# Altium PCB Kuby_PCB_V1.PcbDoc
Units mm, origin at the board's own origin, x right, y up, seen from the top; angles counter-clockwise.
Board outline 122.6 x 93.98 mm, 2 copper layers (Top Layer, Bottom Layer), stack 1.671 mm thick; 16 components, 29 nets, 97 pads, 0 vias.
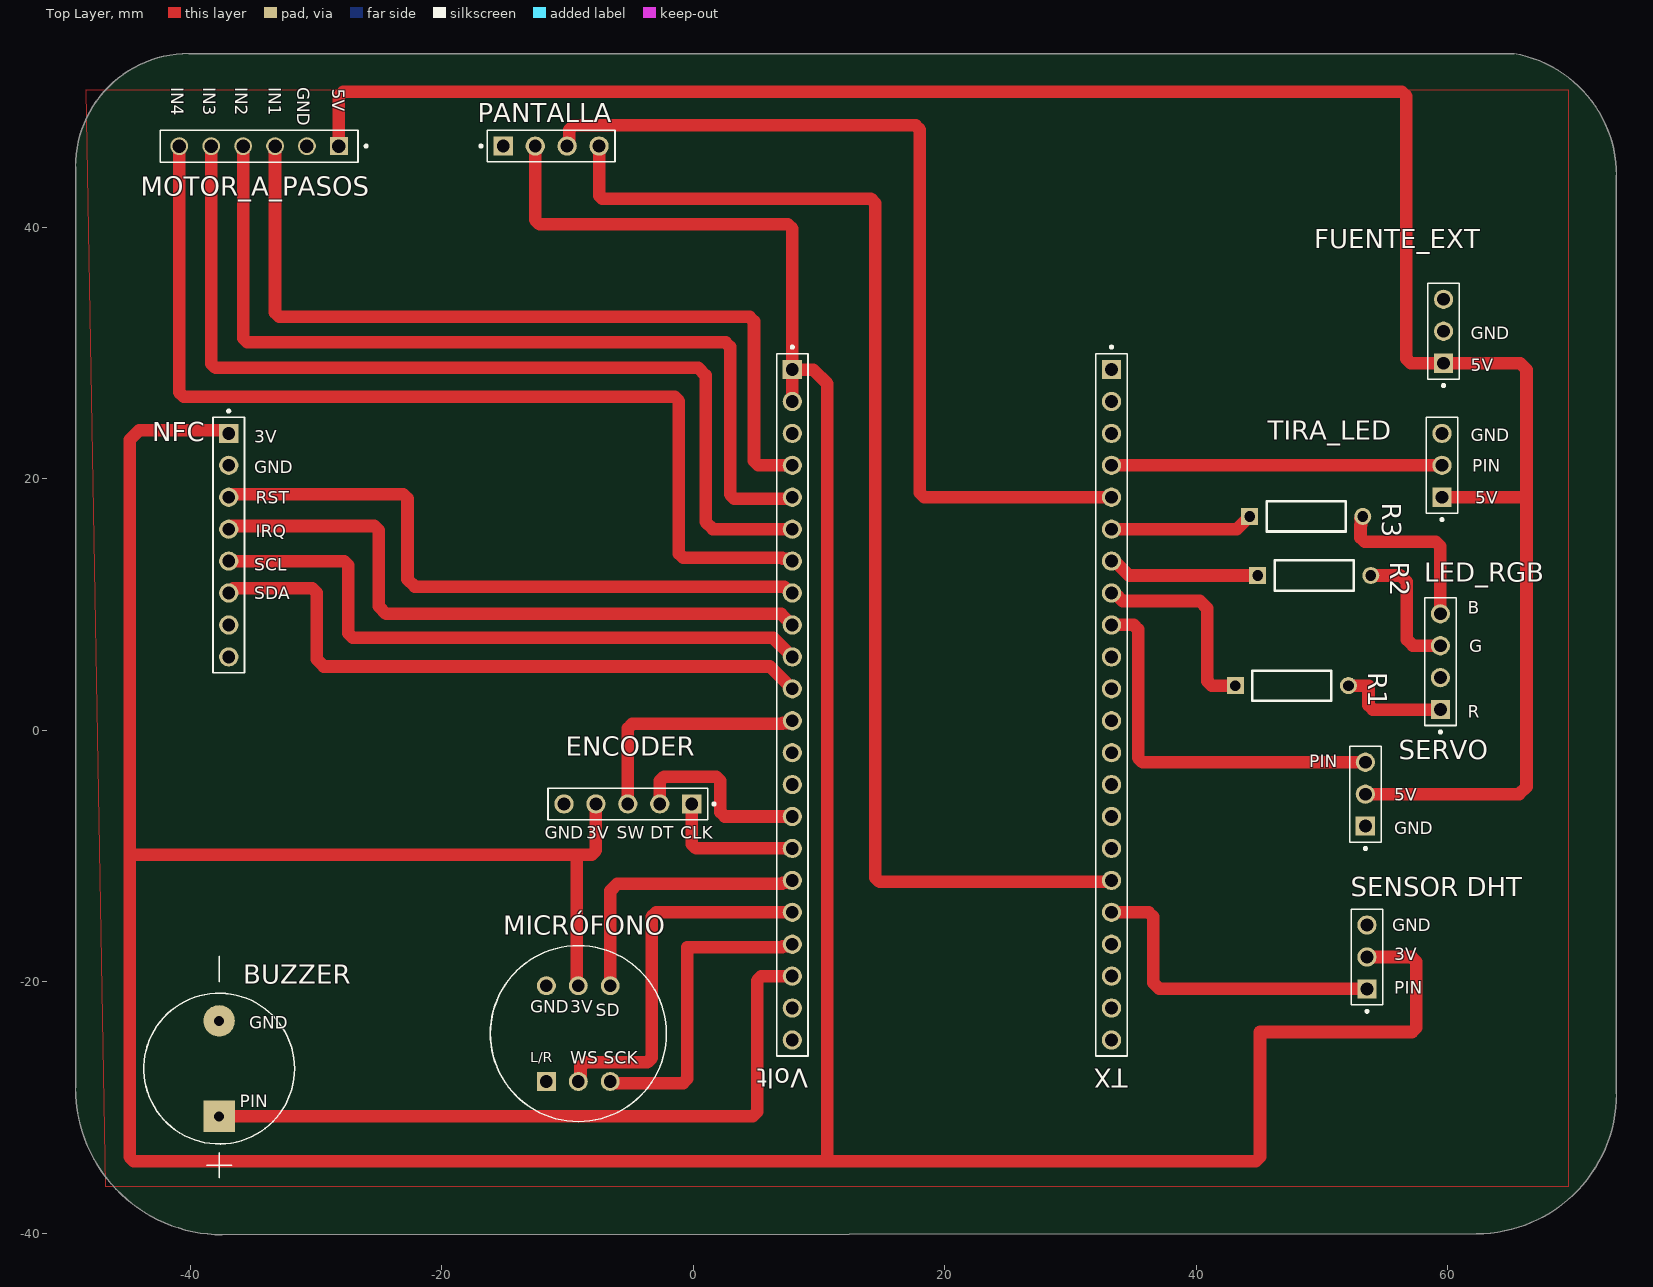
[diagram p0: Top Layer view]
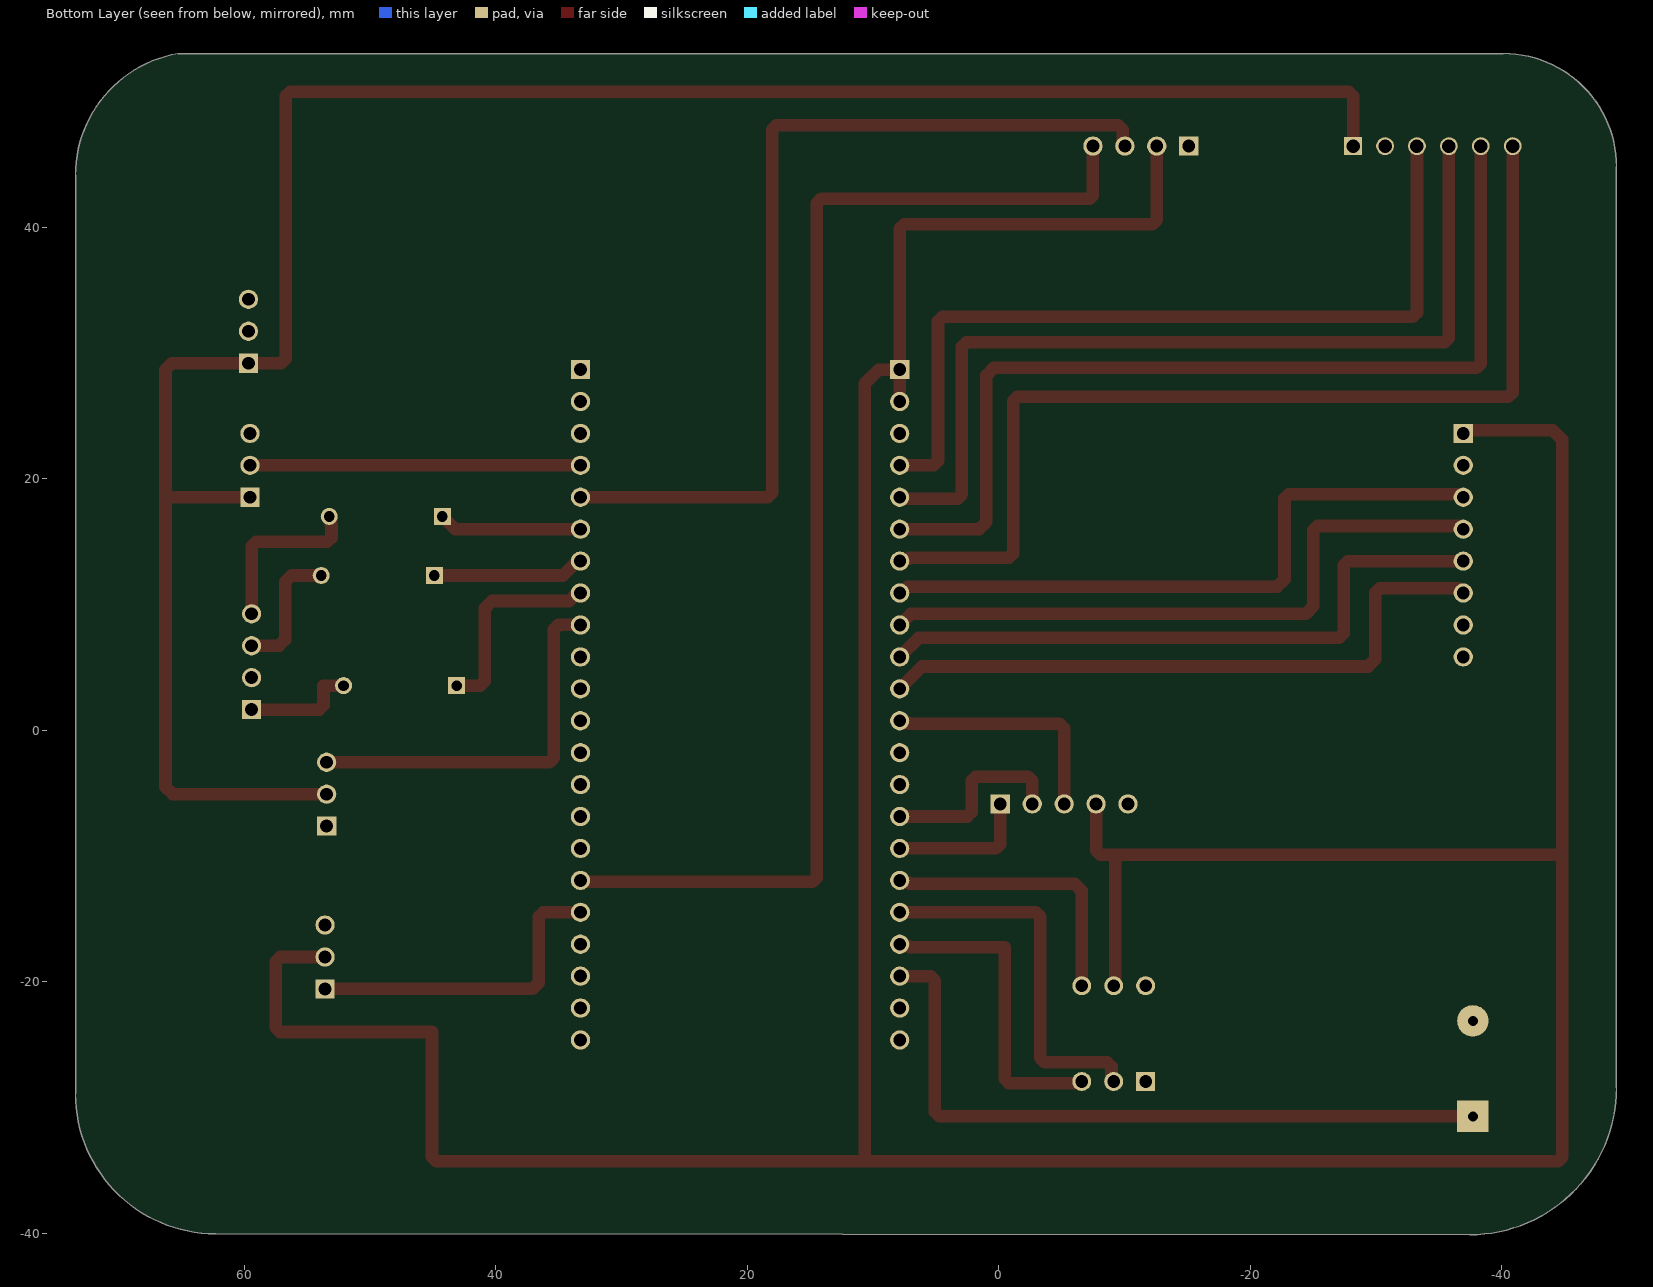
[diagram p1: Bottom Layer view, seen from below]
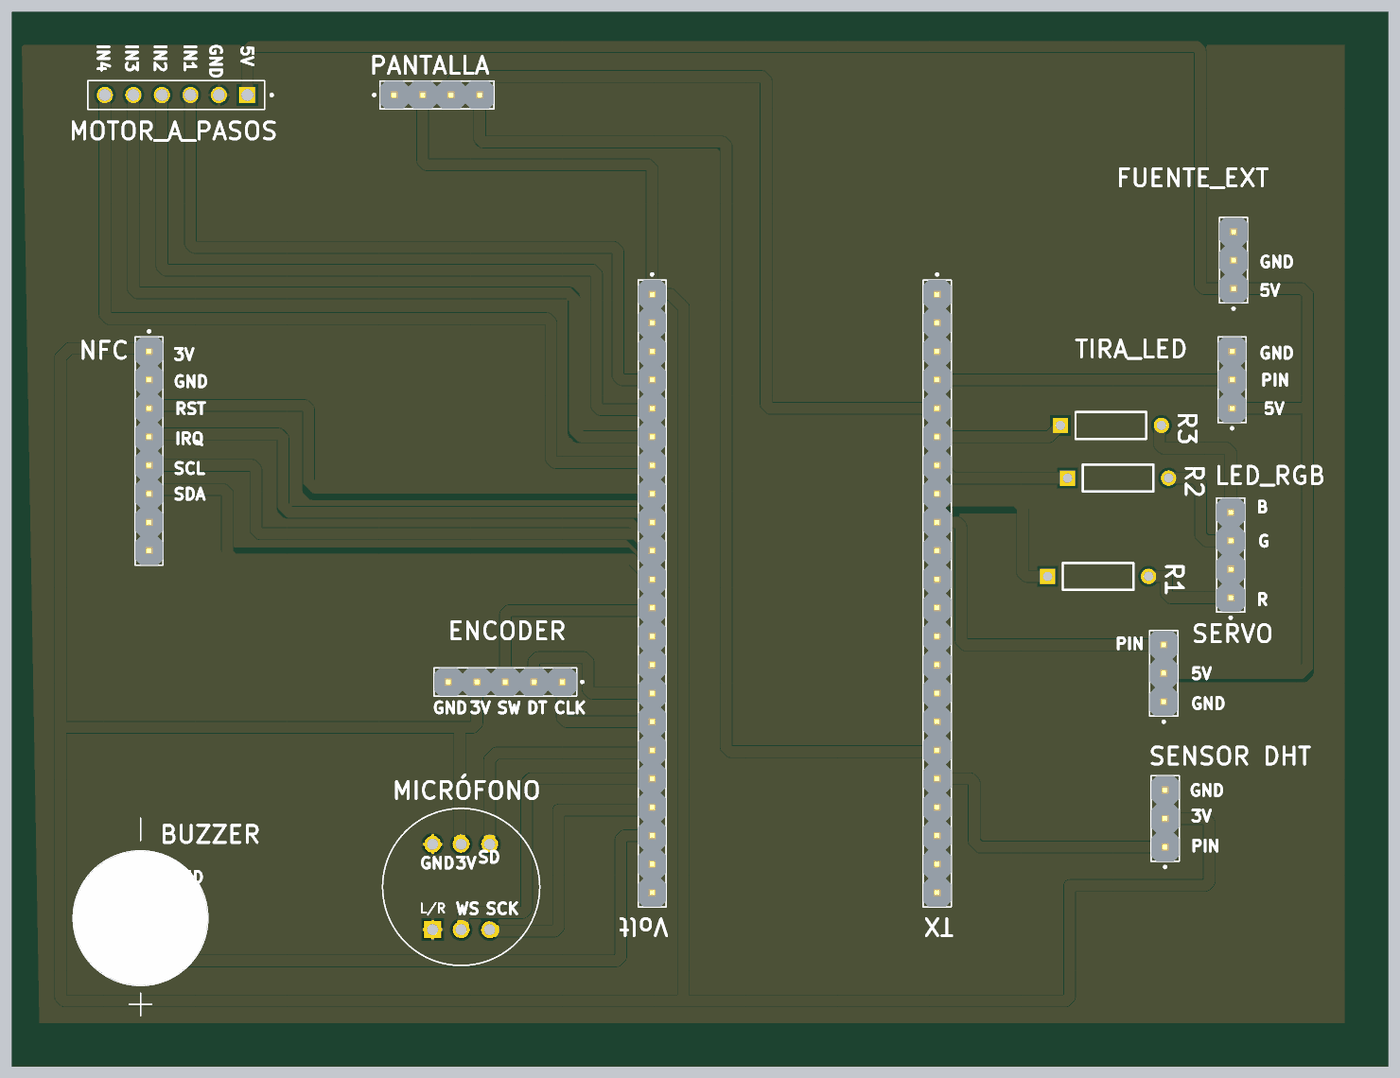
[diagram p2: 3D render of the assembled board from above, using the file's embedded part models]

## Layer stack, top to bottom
Top Solder: solder mask 0.0102, Solder Resist, Dk 3.5
Top Layer: signal copper 0.0356
Dielectric 1: dielectric 1.6, FR-4, Dk 4.8
Bottom Layer: signal copper 0.0356
Bottom Solder: solder mask 0.0102, Solder Resist, Dk 3.5

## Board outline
65.325,53.848 -40.132,53.848 ccw(c-40.132,44.831) -49.149,44.831 -49.149,-28.448 ccw(c-37.468,-28.448) -37.468,-40.129 62.306,-40.06 ccw(c62.298,-28.905) 73.454,-28.905 73.454,44.153 ccw(c63.597,44.144)

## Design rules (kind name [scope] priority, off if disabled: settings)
Clearance [All] p1: gap=0.254 ignorepadtopadclearanceinfootprint=FALSE
PolygonConnect [All] p1: connectstyle=Relief reliefconductorwidth=0.254 reliefentries=4 polygonreliefangle="90 Angle" airgapwidth=0.254
RoutingVias [All] p1: holewidth=0.711 width=1.27 viastyle="Through Hole" minholewidth=0.711 minwidth=1.27 maxholewidth=0.711 maxwidth=1.27
SolderMaskExpansion [All] p1: expansion=0 istentingtop=FALSE
Width [All] p1: maxlimit=3 minlimit=0.254 preferedwidth=1 bottomlayer_maxwidth=0.254 bottomlayer_prefwidth=0.254 minimp=50.000000 maximp=50.000000 favimp=50.000000
30 further rules are at their usual default settings.

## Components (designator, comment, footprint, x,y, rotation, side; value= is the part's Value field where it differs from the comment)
BUZZER "MI-1210-5-95T" XDCR_CMI-1210-5-95T -37.719,-26.914 r90 top
ENCODER "DS1021-1X5SF11-B" CONNFLY_DS1021-1X5SF11-B -5.207,-5.855 r180 top
FUENTE_EXT "DS1021-1X3SF11-B" CONNFLY_DS1021-1X3SF11-B 59.695,31.75 r90 top
LED_RGB "DS1021-1X4SF11-B" CONNFLY_DS1021-1X4SF11-B 59.441,5.461 r90 top
MICRÓFONO "OKY3139" MODULE_OKY3139 -9.144,-24.13 r90 top
MOTOR_A_PASOS "B23-1x6-BG1-G" VALCON_B23-1x6-BG1-G -34.544,46.477 r0 top
NFC "DS1021-1X8SF11-N" CONNFLY_DS1021-1X8SF11-N -36.957,14.732 r270 top
PANTALLA "DS1021-1X4SF11-B" CONNFLY_DS1021-1X4SF11-B -11.303,46.482 r0 top
R1 "" RESA60-630X240 47.625,3.556 r0 top
R2 "" RESA60-630X240 49.403,12.319 r0 top
R3 "" RESA60-630X240 48.768,17.018 r0 top
"SENSOR DHT" "DS1021-1X3SF11-B" CONNFLY_DS1021-1X3SF11-B 53.599,-18.034 r90 top
SERVO "DS1021-1X3SF11-B" CONNFLY_DS1021-1X3SF11-B 53.472,-5.08 r90 top
TIRA_LED "DS1021-1X3SF11-B" CONNFLY_DS1021-1X3SF11-B 59.568,21.082 r90 top
TX "DS1021-1X22SF11-B" CONNFLY_DS1021-1X22SF11-B 33.279,2.032 r270 top
Volt "DS1021-1X22SF11-B" CONNFLY_DS1021-1X22SF11-B 7.879,2.032 r270 top

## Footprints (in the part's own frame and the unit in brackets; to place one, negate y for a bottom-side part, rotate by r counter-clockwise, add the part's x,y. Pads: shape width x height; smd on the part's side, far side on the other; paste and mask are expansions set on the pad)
CONNFLY_DS1021-1X3SF11-B [mm]
  rect 1.53x1.53 / inner round 1.53 / far side rect 1.53x1.53 hole 1.02 mask+0.102: 1(-2.54,0)
  round 1.53 hole 1.02 mask+0.102: 2(0,0) 3(2.54,0)
  silkscreen extent -4.42,-1.25 3.81,1.25, body extent -3.81,-1.25 3.81,1.25, height 8.6
CONNFLY_DS1021-1X4SF11-B [mm]
  rect 1.53x1.53 / inner round 1.53 / far side rect 1.53x1.53 hole 1.02 mask+0.102: 1(-3.81,0)
  round 1.53 hole 1.02 mask+0.102: 2(-1.27,0) 3(1.27,0) 4(3.81,0)
  silkscreen extent -5.69,-1.25 5.08,1.25, body extent -5.08,-1.25 5.08,1.25, height 8.6
CONNFLY_DS1021-1X5SF11-B [mm]
  rect 1.53x1.53 / inner round 1.53 / far side rect 1.53x1.53 hole 1.02 mask+0.102: 1(-5.08,0)
  round 1.53 hole 1.02 mask+0.102: 2(-2.54,0) 3(0,0) 4(2.54,0) 5(5.08,0)
  silkscreen extent -6.96,-1.25 6.35,1.25, body extent -6.35,-1.25 6.35,1.25, height 8.6
CONNFLY_DS1021-1X8SF11-N [mm]
  rect 1.53x1.53 / inner round 1.53 / far side rect 1.53x1.53 hole 1.02 mask+0.102: 1(-8.89,0)
  round 1.53 hole 1.02 mask+0.102: 2(-6.35,0) 3(-3.81,0) 4(-1.27,0) 5(1.27,0) 6(3.81,0) 7(6.35,0) 8(8.89,0)
  silkscreen extent -10.77,-1.25 10.16,1.25, body extent -10.16,-1.25 10.16,1.25, height 8.6
CONNFLY_DS1021-1X22SF11-B [mm]
  rect 1.53x1.53 / inner round 1.53 / far side rect 1.53x1.53 hole 1.02 mask+0.102: 1(-26.67,0)
  round 1.53 hole 1.02 mask+0.102: 2(-24.13,0) 3(-21.59,0) 4(-19.05,0) 5(-16.51,0) 6(-13.97,0) 7(-11.43,0) 8(-8.89,0) 9(-6.35,0) 10(-3.81,0) 11(-1.27,0) 12(1.27,0) 13(3.81,0) 14(6.35,0) 15(8.89,0) 16(11.43,0) 17(13.97,0) 18(16.51,0) 19(19.05,0) 20(21.59,0) 21(24.13,0) 22(26.67,0)
  silkscreen extent -28.55,-1.25 27.94,1.25, body extent -27.94,-1.25 27.94,1.25, height 8.6
MODULE_OKY3139 [mm]
  rect 1.508x1.508 / inner round 1.508 / far side rect 1.508x1.508 hole 1 mask+0.102: 1(-3.81,2.54)
  round 1.508 hole 1 mask+0.102: 2(-3.81,0) 3(-3.81,-2.54) 4(3.81,-2.54) 5(3.81,0) 6(3.81,2.54)
  silkscreen extent -7,-7 7,7
RESA60-630X240 [mm] "Axial Resistor, 2-Leads, Dia 2.4mm, Body Length 6.3mm"
  rect 1.35x1.35 hole 0.85: 1(-4.5,0)
  round 1.35 hole 0.85: 2(4.5,0)
  silkscreen extent -3.15,-1.2 3.15,1.2, body extent -3.15,-1.2 3.15,1.2, height 2.4
VALCON_B23-1x6-BG1-G [mm]
  rect 1.42x1.42 hole 1.07: 01(6.35,0)
  round 1.42 hole 1.07: 02(3.81,0) 03(1.27,0) 04(-1.27,0) 05(-3.81,0) 06(-6.35,0)
  silkscreen extent -7.87,-1.27 8.62,1.27
XDCR_CMI-1210-5-95T [mm]
  round 2.5 hole 0.8: N(3.8,0)
  rect 2.5x2.5 / inner round 2.5 / far side rect 2.5x2.5 hole 0.8: P(-3.8,0)
  silkscreen extent -8.69,-6 8.92,6, body extent -6,-6 6,6, height 7

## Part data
BUZZER: library part CMI-1210-5-95T, "12 mm, 5 Vdc, 98 dB, Through Hole, Magnetic Audio Indicator Buzzer", Package=None
ENCODER: "5 position 2.54mm single row vertical pin header through hole", Package=None
FUENTE_EXT "SENSOR DHT" SERVO TIRA_LED: "3 position 2.54mm single row vertical pin header through hole", Package=None
LED_RGB PANTALLA: "4 position 2.54mm single row vertical pin header through hole", Package=None
MICRÓFONO: "Module: audio; microphone; I2S; IC: INMP441; SNR: 61dB; 60HzÃ·15kHz", Package=None
MOTOR_A_PASOS: Package=None
NFC: "8 position 2.54mm single row vertical pin header through hole", Package=None
R1 R2 R3: library part CMP-1659-00071-1, "Axial Resistor, 100 Ohm, +/- 1%, 0.25 W, -55 to 155 degC, 2-Pin THD, RoHS, Bulk", Case\Package=Axial, Max Operating Temperature="155 degC", Min Operating Temperature="-55 degC", Package Quantity=200, Power Rating="250 mW", Resistance="4.75 kohm", Tolerance=1%, Type (Resistor)="Metal Film", Voltage Rating="250 V"
TX Volt: "22 position 2.54mm single row vertical pin header through hole", Manufacturer=Connfly

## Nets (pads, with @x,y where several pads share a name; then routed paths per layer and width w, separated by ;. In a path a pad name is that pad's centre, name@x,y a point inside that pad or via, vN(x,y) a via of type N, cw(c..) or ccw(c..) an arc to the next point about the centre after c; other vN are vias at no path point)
3V3: "SENSOR DHT.2" ENCODER.4 MICRÓFONO.5 NFC.1 PANTALLA.2 Volt.1 Volt.2 | length 344.2
  Top Layer w1: NFC.1@-36.957,23.876 -44.069,23.876 -44.844,23.101 -44.844,-9.906 ; -35.319,-34.29 -44.493,-34.29 -44.844,-33.939 -44.844,-9.906 ; -35.306,-34.29 10.673,-34.29 ; PANTALLA.2 -12.573,40.61 -12.222,40.259 7.528,40.259 7.879,39.908 Volt.1 ; MICRÓFONO.5 -9.271,-20.193 -9.271,-9.906 ; ENCODER.4 -7.747,-9.555 -8.098,-9.906 -9.271,-9.906 ; Volt.2 Volt.1 ; 53.599,-18.034 57.155,-18.034 57.536,-18.415 57.536,-23.652 57.185,-24.003 45.09,-24.003 45.09,-33.939 44.739,-34.29 10.673,-34.29 ; -44.844,-9.906 -9.271,-9.906 ; Volt.1 9.544,28.702 10.673,27.573 10.673,-34.29
5V: FUENTE_EXT.1 MOTOR_A_PASOS.01 SERVO.2 TIRA_LED.1 | length 173.1
  Top Layer w1: MOTOR_A_PASOS.01 -28.194,50.449 -27.843,50.8 56.376,50.8 56.728,50.449 56.728,29.561 57.079,29.21 FUENTE_EXT.1 65.786,29.21 66.294,28.702 66.294,18.893 ; SERVO.2 65.708,-5.08 66.294,-4.494 66.294,18.893 ; TIRA_LED.1 65.943,18.542 66.294,18.893
BUZZER_PIN: BUZZER.P Volt.20 | length 56.3
  Top Layer w1: BUZZER.P 4.729,-30.714 5.08,-30.363 5.08,-19.909 5.431,-19.558 Volt.20
DHT_PIN: "SENSOR DHT.1" TX.18 | length 25.9
  Top Layer w1: TX.18 36.23,-14.478 36.581,-14.829 36.581,-20.066 37.089,-20.574 53.599,-20.574
ENCODER_CLK: ENCODER.1 Volt.16 | length 11.3
  Top Layer w1: ENCODER.1 -0.127,-9.047 0.224,-9.398 Volt.16
ENCODER_DT: ENCODER.2 Volt.15 | length 15.3
  Top Layer w1: ENCODER.2 -2.667,-4.034 -2.316,-3.683 1.808,-3.683 2.159,-4.034 2.159,-6.507 2.51,-6.858 Volt.15
ENCODER_SW: ENCODER.3 Volt.12 | length 19.3
  Top Layer w1: ENCODER.3 -5.207,0.157 -4.856,0.508 7.063,0.508 7.139,0.584 7.701,0.584 Volt.12
GND: "SENSOR DHT.3" BUZZER.N ENCODER.5 FUENTE_EXT.2 MICRÓFONO.1 MICRÓFONO.6 MOTOR_A_PASOS.02 NFC.2 PANTALLA.1 SERVO.1 TIRA_LED.3 TX.21 TX.22
LED_B: R3.1 TX.6 | length 11.4
  Top Layer w1: TX.6 43.252,16.002 R3.1
LED_G: R2.1 TX.7 | length 12.1
  Top Layer w1: TX.7 33.531,13.462 34.674,12.319 R2.1
LED_R: R1.1 TX.8 | length 16.3
  Top Layer w1: TX.8 33.422,10.922 33.687,10.657 33.796,10.657 34.166,10.287 40.308,10.287 40.894,9.701 40.894,3.907 41.245,3.556 R1.1
MIC_SCK: MICRÓFONO.3 Volt.19 | length 25.2
  Top Layer w1: MICRÓFONO.3 -6.477,-28.067 -0.813,-28.067 -0.462,-27.716 -0.462,-17.272 7.063,-17.272 7.139,-17.196 7.701,-17.196 Volt.19
MIC_SD: MICRÓFONO.4 Volt.17 | length 22.4
  Top Layer w1: MICRÓFONO.4 -6.604,-12.768 -6.028,-12.192 7.063,-12.192 7.139,-12.116 7.701,-12.116 Volt.17
MIC_WS: MICRÓFONO.2 Volt.18 | length 29.8
  Top Layer w1: MICRÓFONO.2 -8.97,-27.766 -8.97,-26.767 -8.619,-26.416 -3.653,-26.416 -3.302,-26.065 -3.302,-14.829 -2.951,-14.478 Volt.18
MOTOR_IN1: MOTOR_A_PASOS.03 Volt.4 | length 65.9
  Top Layer w1: MOTOR_A_PASOS.03 -33.274,33.244 -32.923,32.893 4.48,32.893 4.831,32.542 4.831,21.433 5.183,21.082 Volt.4
MOTOR_IN2: MOTOR_A_PASOS.04 Volt.5 | length 71.2
  Top Layer w1: MOTOR_A_PASOS.04 -35.814,31.212 -35.463,30.861 2.575,30.861 2.926,30.51 2.926,18.766 3.278,18.415 7.752,18.415 Volt.5
MOTOR_IN3: MOTOR_A_PASOS.05 Volt.6 | length 75.8
  Top Layer w1: MOTOR_A_PASOS.05 -38.354,29.18 -38.003,28.829 0.401,28.829 0.986,28.243 0.986,16.588 1.572,16.002 Volt.6
MOTOR_IN4: MOTOR_A_PASOS.06 Volt.7 | length 81
  Top Layer w1: MOTOR_A_PASOS.06 -40.894,26.894 -40.543,26.543 -1.489,26.543 -1.138,26.192 -1.138,14.067 -0.786,13.716 7.063,13.716 7.139,13.64 7.701,13.64 Volt.7
NetLED_RGB_1: LED_RGB.1 R1.2 | length 9
  Top Layer w1: R1.2 53.721,3.556 53.721,2.002 54.072,1.651 LED_RGB.1
NetLED_RGB_3: LED_RGB.3 R2.2 | length 10.5
  Top Layer w1: R2.2 56.261,12.319 56.769,11.811 56.769,7.209 57.247,6.731 LED_RGB.3
NetLED_RGB_4: LED_RGB.4 R3.2 | length 13.6
  Top Layer w1: R3.2@53.086,16.862 53.124,16.824 53.124,16.344 53.086,16.306 53.086,15.337 53.437,14.986 59.085,14.986 59.441,14.629 LED_RGB.4
PAN_SCL: PANTALLA.3 TX.5 | length 73.8
  Top Layer w1: PANTALLA.3 -9.855,46.66 -9.855,47.792 -9.515,48.133 17.683,48.133 18.034,47.782 18.034,18.893 18.385,18.542 TX.5
PAN_SDA: PANTALLA.4 TX.17 | length 98.8
  Top Layer w1: PANTALLA.4 -7.493,42.545 -7.239,42.291 14.127,42.291 14.478,41.94 14.478,-11.714 14.829,-12.065 33.152,-12.065 TX.17
PN532_IRQ: NFC.4 Volt.9 | length 51.7
  Top Layer w1: NFC.4 -36.703,16.256 -25.37,16.256 -25.019,15.905 -25.019,9.857 -24.433,9.271 6.99,9.271 Volt.9
PN532_RST: NFC.3 Volt.8 | length 52
  Top Layer w1: NFC.3 -36.703,18.796 -23.084,18.796 -22.733,18.445 -22.733,12.016 -22.147,11.43 7.228,11.43 7.736,10.922 Volt.8
PN532_SCL: NFC.5 Volt.10 | length 51.3
  Top Layer w1: NFC.5@-37.146,13.462 -27.783,13.462 -27.432,13.111 -27.432,7.717 -27.081,7.366 6.355,7.366 Volt.10
PN532_SDA: NFC.6 Volt.11 | length 51.4
  Top Layer w1: NFC.6 -36.576,11.303 -30.323,11.303 -29.972,10.952 -29.972,5.666 -29.386,5.08 6.101,5.08 Volt.11
SERVO_PIN: SERVO.3 TX.9 | length 30.7
  Top Layer w1: TX.9 35.047,8.382 35.398,8.031 35.398,-2.189 35.75,-2.54 SERVO.3
TIRA_LED_PIN: TIRA_LED.2 TX.4 | length 26.3
  Top Layer w1: TX.4 TIRA_LED.2
pads on no net: FUENTE_EXT.3 LED_RGB.2 NFC.7 NFC.8 TX.1 TX.2 TX.3 TX.10 TX.11 TX.12 TX.13 TX.14 TX.15 TX.16 TX.19 TX.20 Volt.3 Volt.13 Volt.14 Volt.21 Volt.22

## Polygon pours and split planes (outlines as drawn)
GND on Top Layer "NONET_L01_P-001" (solid, remove dead copper, shelved, pour order 0): -48.3,50.954 69.596,50.954 69.596,-36.295 -46.74,-36.295

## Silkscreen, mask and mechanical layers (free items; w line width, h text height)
Top Overlay:
  text "IN4" at -41.529,51.181 h1 r270
  text "IN3" at -38.989,51.176 h1 r270
  text "IN2" at -36.449,51.176 h1 r270
  text "IN1" at -33.782,51.176 h1 r270
  text "GND" at -31.496,51.176 h1 r270
  text "5V" at -28.702,51.049 h1 r270
  text "GND" at 61.854,31.115 h1
  text "5V" at 61.854,28.575 h1
  text "GND" at 61.854,22.987 h1
  text "3V" at -34.92,22.86 h1
  text "PIN" at 61.981,20.574 h1
  text "GND" at -34.92,20.447 h1
  text "RST" at -34.793,18.034 h1
  text "5V" at 62.235,18.034 h1
  text "IRQ" at -34.793,15.367 h1
  text "SCL" at -34.92,12.7 h1
  text "SDA" at -34.92,10.414 h1
  text "B" at 61.6,9.271 h1
  text "G" at 61.727,6.223 h1
  text "R" at 61.6,1.016 h1
  text "PIN" at 49.022,-2.921 h1
  text "5V" at 55.758,-5.588 h1
  text "GND" at 55.758,-8.255 h1
  text "GND" at -11.811,-8.636 h1
  text "3V" at -8.509,-8.636 h1
  text "SW" at -6.096,-8.636 h1
  text "DT" at -3.429,-8.636 h1
  text "CLK" at -1.016,-8.636 h1
  text "GND" at 55.631,-16.002 h1
  text "3V" at 55.758,-18.288 h1
  text "PIN" at 55.758,-20.955 h1
  text "GND" at -12.954,-22.479 h1
  text "3V" at -9.779,-22.479 h1
  text "SD" at -7.747,-22.733 h1
  text "GND" at -35.306,-23.749 h1
  text "WS" at -9.779,-26.543 h1
  text "SCK" at -7.112,-26.543 h1
  text "PIN" at -36.068,-29.972 h1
